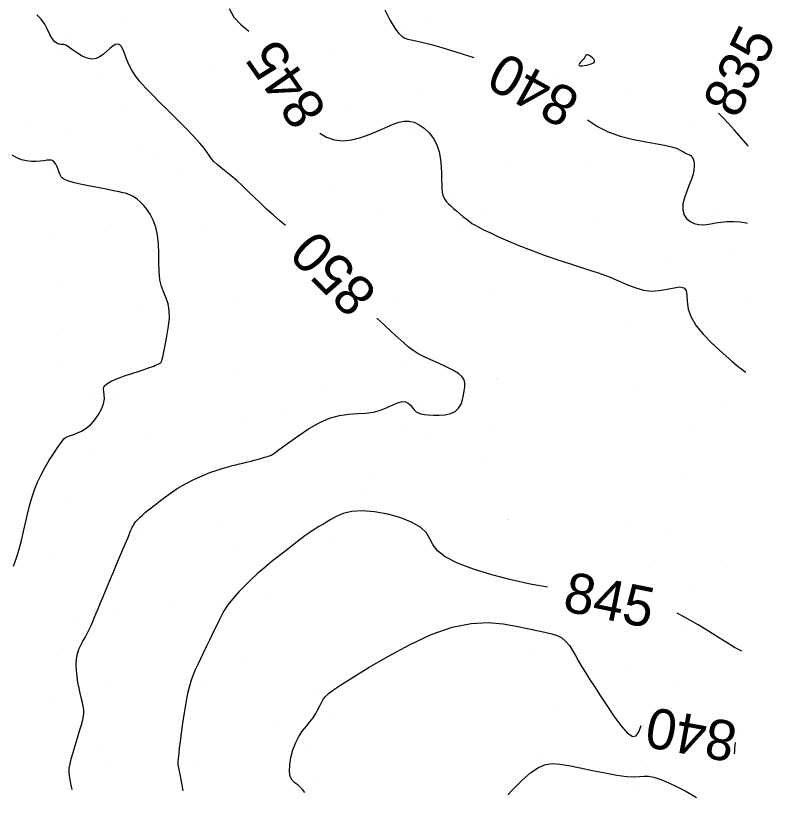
# Model space of a CAD drawing. Extents: x 400243 to 403697, y 4403637 to 4408083.
# Drawn here: x 402954.4 to 403095.7, y 4405853 to 4405998.7 of the extents above; entities that cross this region are included whole.
import ezdxf

# ---------------------------------------------------------------- set-up
doc = ezdxf.new("R2010")
doc.units = 0
doc.layers.add('HH_DiS', color=7, linetype='Continuous')
doc.layers.add('HH_IC', color=7, linetype='Continuous')

msp = doc.modelspace()

# ---------------------------------------------------------------- linework, layer by layer
at = {"layer": 'HH_DiS'}
msp.add_line((403004.38, 4405924.73), (403004.38, 4405924.73), dxfattribs=at)
at = {"layer": 'HH_IC'}
for p, q in [((402974.1, 4405998.57), (402974.1, 4405998.57)), ((403031.74, 4405998.14), (403031.74, 4405998.14)), ((403027, 4405995.77), (403027, 4405995.77)), ((402963.64, 4405994.12), (402963.64, 4405994.12)), ((402963.91, 4405994.25), (402963.91, 4405994.25)), ((403013.43, 4405992.67), (403013.43, 4405992.67)), ((402963.29, 4405991.89), (402963.29, 4405991.89)), ((403086.84, 4405991.77), (403086.84, 4405991.77)), ((403061.02, 4405990.08), (403061.02, 4405990.08)), ((403085.9, 4405990.13), (403085.9, 4405990.13)), ((402970.34, 4405987.96), (402970.34, 4405987.96)), ((402991.13, 4405989.31), (402991.13, 4405989.31)), ((403054.48, 4405987.14), (403054.48, 4405987.14)), ((403029.23, 4405985.05), (403029.23, 4405985.05)), ((403068.85, 4405984.25), (403068.85, 4405984.25)), ((402974.71, 4405981.67), (402974.71, 4405981.67)), ((403016.53, 4405981.52), (403016.53, 4405981.52)), ((403085.02, 4405981.59), (403085.02, 4405981.59)), ((402956.59, 4405978.42), (402956.59, 4405978.42)), ((403080.48, 4405978.69), (403080.48, 4405978.69)), ((402963.85, 4405977.37), (402963.85, 4405977.37)), ((403028.05, 4405977.16), (403028.05, 4405977.16)), ((402978.31, 4405974.53), (402978.31, 4405974.53)), ((402980.08, 4405972.86), (402980.08, 4405972.86)), ((403079.57, 4405971.96), (403079.57, 4405971.96)), ((403046.52, 4405970.77), (403046.52, 4405970.77)), ((403061.14, 4405970.51), (403061.14, 4405970.51)), ((402961.03, 4405970.24), (402961.03, 4405970.24)), ((402985.24, 4405969.68), (402985.24, 4405969.68)), ((402962.63, 4405967.53), (402962.63, 4405967.53)), ((403013.25, 4405966.29), (403013.25, 4405966.29)), ((403035.13, 4405964.99), (403035.13, 4405964.99)), ((403084.27, 4405962.3), (403084.27, 4405962.3)), ((403022.5, 4405961.45), (403022.5, 4405961.45)), ((403041, 4405961.61), (403041, 4405961.61)), ((403062.6, 4405960.83), (403062.6, 4405960.83)), ((402961.38, 4405957.97), (402961.38, 4405957.97)), ((402970.96, 4405958.57), (402970.96, 4405958.57)), ((402988.94, 4405958.63), (402988.94, 4405958.63)), ((403037.24, 4405958.48), (403037.24, 4405958.48)), ((403013.31, 4405957.18), (403013.31, 4405957.18)), ((403088.07, 4405955.16), (403088.07, 4405955.16)), ((403076.03, 4405952.46), (403076.03, 4405952.46)), ((402961.92, 4405949.02), (402961.92, 4405949.02)), ((403018.52, 4405949.85), (403018.52, 4405949.85)), ((403025.07, 4405945.86), (403025.07, 4405945.86)), ((403042.5, 4405946.79), (403042.5, 4405946.79)), ((402977.32, 4405944.53), (402977.32, 4405944.53)), ((402995.62, 4405945.07), (402995.62, 4405945.07)), ((403013.71, 4405945.64), (403013.71, 4405945.64)), ((403090.67, 4405945.08), (403090.67, 4405945.08)), ((402963.38, 4405940.47), (402963.38, 4405940.47)), ((403069.11, 4405941.1), (403069.11, 4405941.1)), ((402963.26, 4405934), (402963.26, 4405934)), ((402980.17, 4405934.22), (402980.17, 4405934.22)), ((403027.5, 4405933.5), (403027.5, 4405933.5)), ((402994.79, 4405932.51), (402994.79, 4405932.51)), ((403044.17, 4405931.04), (403044.17, 4405931.04)), ((403044.19, 4405931.01), (403044.19, 4405931.01)), ((402968.13, 4405928.35), (402968.13, 4405928.35)), ((403011.24, 4405928.82), (403011.24, 4405928.82)), ((403070.31, 4405929.58), (403070.31, 4405929.58)), ((402972.65, 4405927.9), (402972.65, 4405927.9)), ((403086.67, 4405927.06), (403086.67, 4405927.06)), ((403029.73, 4405926.68), (403029.73, 4405926.68)), ((402996.29, 4405923.79), (402996.29, 4405923.79)), ((403026.75, 4405921.4), (403026.75, 4405921.4)), ((403043.19, 4405922.04), (403043.19, 4405922.04)), ((403079.98, 4405921.35), (403079.98, 4405921.35)), ((402979.51, 4405920.8), (402979.51, 4405920.8)), ((403031.95, 4405920.16), (403031.95, 4405920.16)), ((402969.1, 4405917.84), (402969.1, 4405917.84)), ((403001.9, 4405917.02), (403001.9, 4405917.02)), ((403042.41, 4405916.17), (403042.41, 4405916.17)), ((402996.45, 4405913.7), (402996.45, 4405913.7)), ((403020.92, 4405913.16), (403020.92, 4405913.16)), ((403078.99, 4405912.58), (403078.99, 4405912.58)), ((403018.8, 4405909.87), (403018.8, 4405909.87)), ((402964.19, 4405908.04), (402964.19, 4405908.04)), ((403046.07, 4405904.85), (403046.07, 4405904.85)), ((403046.11, 4405904.85), (403046.11, 4405904.85)), ((403068.63, 4405904.3), (403068.63, 4405904.3)), ((402978.14, 4405902.59), (402978.14, 4405902.59)), ((402992.43, 4405903.24), (402992.43, 4405903.24)), ((403076.35, 4405903.07), (403076.35, 4405903.07)), ((403013.18, 4405901.45), (403013.18, 4405901.45)), ((402995.71, 4405899.82), (402995.71, 4405899.82)), ((402961.41, 4405897.89), (402961.41, 4405897.89)), ((403073.66, 4405897.04), (403073.66, 4405897.04)), ((403085.87, 4405897.21), (403085.87, 4405897.21)), ((403051.71, 4405893.53), (403051.71, 4405893.53)), ((403081.19, 4405892.55), (403081.19, 4405892.55)), ((403068.76, 4405890.26), (403068.76, 4405890.26)), ((402983.17, 4405889.37), (402983.17, 4405889.37)), ((403001.71, 4405889.91), (403001.71, 4405889.91)), ((402973.67, 4405887.81), (402973.67, 4405887.81)), ((402992.21, 4405888.7), (402992.21, 4405888.7)), ((402966.01, 4405885.65), (402966.01, 4405885.65)), ((403078.8, 4405884.24), (403078.8, 4405884.24)), ((402963.33, 4405880.79), (402963.33, 4405880.79)), ((403050.97, 4405880.12), (403050.97, 4405880.12)), ((402996.64, 4405878.4), (402996.64, 4405878.4)), ((403068.31, 4405876.46), (403068.31, 4405876.46)), ((402971.71, 4405874.06), (402971.71, 4405874.06)), ((402989.45, 4405873.69), (402989.45, 4405873.69)), ((403077.71, 4405873.62), (403077.71, 4405873.62)), ((402961.34, 4405871.63), (402961.34, 4405871.63)), ((403010.94, 4405872.73), (403010.94, 4405872.73)), ((402966.44, 4405868.65), (402966.44, 4405868.65)), ((403013.43, 4405868.54), (403013.43, 4405868.54)), ((403055.42, 4405869.13), (403055.42, 4405869.13)), ((403003.19, 4405866.18), (403003.19, 4405866.18)), ((403089.02, 4405865.66), (403089.02, 4405865.66)), ((403074.34, 4405862.88), (403074.34, 4405862.88)), ((402970.61, 4405862.02), (402970.61, 4405862.02)), ((403009.2, 4405861.7), (403009.2, 4405861.7)), ((403051.58, 4405860.63), (403051.58, 4405860.63)), ((403070.85, 4405859.86), (403070.85, 4405859.86)), ((402972.23, 4405859.08), (402972.23, 4405859.08)), ((402987.36, 4405859.23), (402987.36, 4405859.23)), ((403010.01, 4405856.69), (403010.01, 4405856.69)), ((403070.61, 4405855.18), (403070.61, 4405855.18))]:
    msp.add_line(p, q, dxfattribs=at)
for points in [[(402994.21, 4406000.04), (402995.1, 4405998.47), (402996.4, 4405997.09), (402997.85, 4405995.83)], [(403023.24, 4405999.81), (403024.26, 4405997.82), (403025.11, 4405996.39), (403025.81, 4405995.45), (403026.42, 4405994.88), (403026.98, 4405994.56), (403027.54, 4405994.38), (403028.18, 4405994.23), (403029, 4405994.06), (403030.13, 4405993.8), (403031.71, 4405993.39), (403033.86, 4405992.78), (403036.65, 4405991.93), (403039.84, 4405990.92)], [(403004.72, 4405959.59), (403003.58, 4405960.55), (403002.4, 4405961.57), (403001.2, 4405962.63), (403000.03, 4405963.74), (402998.88, 4405964.86), (402997.76, 4405965.96), (402996.68, 4405967.02), (402995.61, 4405967.99), (402994.59, 4405968.87), (402993.62, 4405969.64), (402992.74, 4405970.34), (402991.98, 4405970.96), (402991.37, 4405971.52), (402990.92, 4405972.04), (402990.54, 4405972.58), (402990.12, 4405973.21), (402989.54, 4405974.01), (402988.69, 4405975.03), (402987.5, 4405976.32), (402986.05, 4405977.81), (402984.44, 4405979.42), (402982.8, 4405981.05), (402981.23, 4405982.61), (402979.82, 4405984.02), (402978.6, 4405985.3), (402977.56, 4405986.48), (402976.68, 4405987.6), (402975.98, 4405988.68), (402975.44, 4405989.76), (402975.02, 4405990.79), (402974.68, 4405991.72), (402974.38, 4405992.49), (402974.08, 4405993.05), (402973.75, 4405993.36), (402973.37, 4405993.44), (402972.94, 4405993.33), (402972.48, 4405993.04), (402971.96, 4405992.63), (402971.4, 4405992.11), (402970.79, 4405991.57), (402970.12, 4405991.09), (402969.38, 4405990.76), (402968.57, 4405990.65), (402967.7, 4405990.82), (402966.8, 4405991.21), (402965.93, 4405991.72), (402965.15, 4405992.24), (402964.52, 4405992.7), (402964.08, 4405993.02), (402963.77, 4405993.21), (402963.55, 4405993.3), (402963.36, 4405993.33), (402963.14, 4405993.33), (402962.83, 4405993.34), (402962.46, 4405993.41), (402962.05, 4405993.59), (402961.62, 4405993.92), (402961.19, 4405994.47), (402960.78, 4405995.24), (402960.34, 4405996.17), (402959.82, 4405997.16), (402959.16, 4405998.1), (402958.32, 4405998.9)], [(403059.48, 4405989.43), (403059.69, 4405989.35), (403060.03, 4405989.36), (403060.45, 4405989.41), (403060.91, 4405989.51), (403061.36, 4405989.62), (403061.74, 4405989.74), (403062.05, 4405989.87), (403062.26, 4405990.01), (403062.36, 4405990.18), (403062.34, 4405990.39), (403062.2, 4405990.63), (403061.96, 4405990.88), (403061.68, 4405991.12), (403061.38, 4405991.31), (403061.11, 4405991.41), (403060.9, 4405991.42), (403060.75, 4405991.35), (403060.65, 4405991.23), (403060.58, 4405991.09), (403060.54, 4405990.96), (403060.51, 4405990.87), (403060.48, 4405990.8), (403060.42, 4405990.73), (403060.33, 4405990.63), (403060.19, 4405990.49), (403059.98, 4405990.29), (403059.75, 4405990.05), (403059.56, 4405989.8), (403059.45, 4405989.58), (403059.48, 4405989.43)], [(403061.04, 4405979.28), (403062.88, 4405978.08), (403064.92, 4405977.04), (403067.13, 4405976.25), (403069.4, 4405975.67), (403071.62, 4405975.25), (403073.66, 4405974.91), (403075.4, 4405974.6), (403076.75, 4405974.27), (403077.75, 4405973.93), (403078.47, 4405973.6), (403078.97, 4405973.32), (403079.32, 4405973.09), (403079.58, 4405972.95), (403079.78, 4405972.88), (403079.93, 4405972.83), (403080.06, 4405972.8), (403080.19, 4405972.74), (403080.33, 4405972.64), (403080.47, 4405972.48), (403080.61, 4405972.27), (403080.74, 4405971.98), (403080.85, 4405971.62), (403080.92, 4405971.17), (403080.94, 4405970.63), (403080.88, 4405969.97), (403080.72, 4405969.18), (403080.44, 4405968.25), (403080.03, 4405967.17), (403079.56, 4405965.99), (403079.14, 4405964.78), (403078.85, 4405963.62), (403078.8, 4405962.56), (403079.04, 4405961.66), (403079.53, 4405960.93), (403080.19, 4405960.37), (403080.95, 4405959.98), (403081.74, 4405959.77), (403082.5, 4405959.71), (403083.25, 4405959.78), (403084.04, 4405959.93), (403084.91, 4405960.1), (403085.91, 4405960.24), (403087.05, 4405960.33), (403088.27, 4405960.33), (403089.5, 4405960.26), (403090.65, 4405960.09), (403090.85, 4405960.04)], [(403091.03, 4405974.34), (403090.92, 4405974.49), (403089.73, 4405975.92), (403088.46, 4405977.37), (403087.25, 4405978.71), (403086.22, 4405979.8), (403085.46, 4405980.54)], [(403011.1, 4405976.84), (403012.38, 4405976.06), (403013.81, 4405975.57), (403015.38, 4405975.41), (403017.06, 4405975.59), (403018.78, 4405976.03), (403020.49, 4405976.64), (403022.11, 4405977.31), (403023.57, 4405977.95), (403024.82, 4405978.48), (403025.9, 4405978.86), (403026.87, 4405979.06), (403027.78, 4405979.06), (403028.69, 4405978.85), (403029.65, 4405978.4), (403030.6, 4405977.73), (403031.5, 4405976.86), (403032.3, 4405975.82), (403032.93, 4405974.62), (403033.37, 4405973.31), (403033.63, 4405971.94), (403033.77, 4405970.57), (403033.82, 4405969.29), (403033.84, 4405968.14), (403033.86, 4405967.19), (403033.9, 4405966.42), (403033.96, 4405965.79), (403034.08, 4405965.27), (403034.24, 4405964.82), (403034.47, 4405964.41), (403034.76, 4405964.02), (403035.12, 4405963.64), (403035.55, 4405963.24), (403036.04, 4405962.8), (403036.58, 4405962.32), (403037.17, 4405961.82), (403037.78, 4405961.31), (403038.38, 4405960.82), (403038.96, 4405960.38), (403039.49, 4405960), (403040.06, 4405959.64), (403040.75, 4405959.26), (403041.64, 4405958.82), (403042.81, 4405958.27), (403044.33, 4405957.57), (403046.17, 4405956.77), (403048.26, 4405955.89), (403050.55, 4405954.98), (403052.98, 4405954.08), (403055.5, 4405953.22), (403058.03, 4405952.4), (403060.5, 4405951.61), (403062.84, 4405950.83), (403064.98, 4405950.06), (403066.85, 4405949.29), (403068.52, 4405948.56), (403070.04, 4405947.96), (403071.49, 4405947.54), (403072.94, 4405947.36), (403074.42, 4405947.46), (403075.87, 4405947.72), (403077.19, 4405947.99), (403078.28, 4405948.14), (403079.04, 4405948), (403079.42, 4405947.47), (403079.55, 4405946.58), (403079.63, 4405945.41), (403079.84, 4405944.03), (403080.37, 4405942.5), (403081.33, 4405940.91), (403082.63, 4405939.31), (403084.1, 4405937.79), (403085.59, 4405936.4), (403086.92, 4405935.23), (403087.98, 4405934.32), (403088.78, 4405933.64), (403089.38, 4405933.15), (403089.85, 4405932.79), (403090.23, 4405932.52), (403090.5, 4405932.34), (403090.58, 4405932.29)], [(402953.99, 4405896.07), (402954.55, 4405897.63), (402955.03, 4405899.25), (402955.45, 4405900.89), (402955.84, 4405902.54), (402956.21, 4405904.18), (402956.58, 4405905.78), (402956.98, 4405907.33), (402957.42, 4405908.83), (402957.91, 4405910.29), (402958.48, 4405911.72), (402959.13, 4405913.13), (402959.87, 4405914.51), (402960.66, 4405915.82), (402961.43, 4405917.02), (402962.12, 4405918.05), (402962.69, 4405918.87), (402963.1, 4405919.44), (402963.39, 4405919.8), (402963.66, 4405920.04), (402963.97, 4405920.2), (402964.41, 4405920.35), (402965.02, 4405920.56), (402965.79, 4405920.86), (402966.64, 4405921.26), (402967.53, 4405921.8), (402968.39, 4405922.5), (402969.18, 4405923.37), (402969.85, 4405924.35), (402970.38, 4405925.37), (402970.75, 4405926.37), (402970.93, 4405927.27), (402970.92, 4405928.01), (402970.82, 4405928.63), (402970.77, 4405929.15), (402970.91, 4405929.63), (402971.36, 4405930.1), (402972.22, 4405930.58), (402973.38, 4405931.08), (402974.7, 4405931.56), (402976.03, 4405932.01), (402977.21, 4405932.39), (402978.15, 4405932.7), (402978.84, 4405932.93), (402979.37, 4405933.12), (402979.78, 4405933.27), (402980.13, 4405933.4), (402980.46, 4405933.53), (402980.78, 4405933.66), (402981.07, 4405933.8), (402981.32, 4405933.96), (402981.51, 4405934.14), (402981.64, 4405934.35), (402981.73, 4405934.65), (402981.82, 4405935.1), (402981.94, 4405935.75), (402982.12, 4405936.66), (402982.37, 4405937.88), (402982.66, 4405939.31), (402982.91, 4405940.84), (402983.06, 4405942.37), (402983.04, 4405943.77), (402982.82, 4405944.99), (402982.46, 4405946.07), (402982.02, 4405947.12), (402981.61, 4405948.23), (402981.29, 4405949.5), (402981.13, 4405951.01), (402981.08, 4405952.68), (402981.07, 4405954.43), (402981.02, 4405956.18), (402980.85, 4405957.82), (402980.52, 4405959.3), (402980.05, 4405960.59), (402979.47, 4405961.7), (402978.85, 4405962.65), (402978.21, 4405963.42), (402977.61, 4405964.03), (402977.04, 4405964.5), (402976.53, 4405964.86), (402976.06, 4405965.12), (402975.65, 4405965.32), (402975.29, 4405965.47), (402974.9, 4405965.6), (402974.39, 4405965.72), (402973.67, 4405965.88), (402972.65, 4405966.08), (402971.28, 4405966.35), (402969.67, 4405966.67), (402968, 4405967), (402966.42, 4405967.34), (402965.09, 4405967.64), (402964.13, 4405967.91), (402963.49, 4405968.15), (402963.1, 4405968.4), (402962.86, 4405968.69), (402962.69, 4405969.06), (402962.52, 4405969.51), (402962.33, 4405970.02), (402962.12, 4405970.54), (402961.89, 4405971.01), (402961.64, 4405971.38), (402961.38, 4405971.63), (402961.07, 4405971.76), (402960.69, 4405971.79), (402960.23, 4405971.76), (402959.66, 4405971.69), (402958.97, 4405971.61), (402958.17, 4405971.55), (402957.31, 4405971.55), (402956.4, 4405971.63), (402955.49, 4405971.84), (402954.59, 4405972.19), (402953.71, 4405972.69)], [(402964.94, 4405854.44), (402964.75, 4405855.26), (402964.54, 4405856.22), (402964.41, 4405857.02), (402964.35, 4405857.73), (402964.39, 4405858.43), (402964.52, 4405859.21), (402964.75, 4405860.16), (402965.08, 4405861.33), (402965.48, 4405862.66), (402965.91, 4405864.03), (402966.31, 4405865.34), (402966.65, 4405866.5), (402966.89, 4405867.41), (402967.04, 4405868.12), (402967.1, 4405868.7), (402967.1, 4405869.2), (402967.04, 4405869.7), (402966.93, 4405870.25), (402966.79, 4405870.87), (402966.61, 4405871.58), (402966.42, 4405872.39), (402966.22, 4405873.31), (402966.01, 4405874.35), (402965.83, 4405875.47), (402965.71, 4405876.62), (402965.66, 4405877.75), (402965.72, 4405878.8), (402965.9, 4405879.74), (402966.18, 4405880.58), (402966.54, 4405881.35), (402966.94, 4405882.08), (402967.35, 4405882.8), (402967.74, 4405883.53), (402968.11, 4405884.27), (402968.46, 4405885.02), (402968.79, 4405885.78), (402969.11, 4405886.54), (402969.43, 4405887.31), (402969.76, 4405888.14), (402970.15, 4405889.09), (402970.62, 4405890.24), (402971.19, 4405891.62), (402971.89, 4405893.29), (402972.67, 4405895.12), (402973.46, 4405896.98), (402974.2, 4405898.72), (402974.82, 4405900.2), (402975.29, 4405901.32), (402975.61, 4405902.12), (402975.83, 4405902.67), (402975.99, 4405903.05), (402976.13, 4405903.34), (402976.27, 4405903.61), (402976.43, 4405903.87), (402976.61, 4405904.13), (402976.81, 4405904.38), (402977.04, 4405904.64), (402977.29, 4405904.91), (402977.61, 4405905.22), (402978.04, 4405905.61), (402978.63, 4405906.12), (402979.42, 4405906.77), (402980.44, 4405907.59), (402981.66, 4405908.53), (402983.03, 4405909.53), (402984.52, 4405910.53), (402986.06, 4405911.45), (402987.63, 4405912.26), (402989.16, 4405912.94), (402990.62, 4405913.51), (402991.94, 4405913.97), (402993.09, 4405914.34), (402994.03, 4405914.61), (402994.81, 4405914.82), (402995.48, 4405914.98), (402996.11, 4405915.13), (402996.76, 4405915.28), (402997.47, 4405915.45), (402998.22, 4405915.65), (402998.96, 4405915.85), (402999.67, 4405916.05), (403000.29, 4405916.22), (403000.79, 4405916.37), (403001.19, 4405916.49), (403001.5, 4405916.58), (403001.72, 4405916.66), (403001.89, 4405916.72), (403002.01, 4405916.77), (403002.1, 4405916.8), (403002.16, 4405916.83), (403002.2, 4405916.85), (403002.23, 4405916.87), (403002.28, 4405916.89), (403002.42, 4405916.98), (403002.73, 4405917.2), (403003.3, 4405917.62), (403004.21, 4405918.31), (403005.53, 4405919.29), (403007.17, 4405920.47), (403009.03, 4405921.68), (403010.99, 4405922.8), (403012.94, 4405923.67), (403014.8, 4405924.19), (403016.54, 4405924.44), (403018.17, 4405924.55), (403019.7, 4405924.63), (403021.13, 4405924.81), (403022.45, 4405925.18), (403023.66, 4405925.66), (403024.74, 4405926.15), (403025.68, 4405926.56), (403026.47, 4405926.78), (403027.1, 4405926.73), (403027.6, 4405926.46), (403028.01, 4405926.07), (403028.37, 4405925.62), (403028.71, 4405925.2), (403029.06, 4405924.88), (403029.47, 4405924.65), (403029.97, 4405924.48), (403030.59, 4405924.37), (403031.37, 4405924.3), (403032.33, 4405924.24), (403033.4, 4405924.23), (403034.49, 4405924.32), (403035.51, 4405924.54), (403036.37, 4405924.94), (403037.01, 4405925.53), (403037.45, 4405926.27), (403037.74, 4405927.11), (403037.93, 4405927.97), (403038.05, 4405928.79), (403038.15, 4405929.53), (403038.17, 4405930.19), (403038.02, 4405930.8), (403037.65, 4405931.4), (403036.97, 4405932), (403035.94, 4405932.62), (403034.66, 4405933.26), (403033.26, 4405933.9), (403031.84, 4405934.53), (403030.55, 4405935.13), (403029.47, 4405935.7), (403028.55, 4405936.29), (403027.67, 4405936.94), (403026.77, 4405937.7), (403025.72, 4405938.64), (403024.49, 4405939.78), (403023.12, 4405941.05), (403021.72, 4405942.35)], [(403053.58, 4405892.15), (403050.32, 4405892.73), (403046.78, 4405893.52), (403043.18, 4405894.46), (403039.77, 4405895.52), (403036.79, 4405896.65), (403034.5, 4405897.81), (403033.05, 4405898.96), (403032.2, 4405900.09), (403031.63, 4405901.19), (403031, 4405902.26), (403029.98, 4405903.27), (403028.34, 4405904.23), (403026.2, 4405905.07), (403023.79, 4405905.75), (403021.32, 4405906.2), (403019.02, 4405906.38), (403017.07, 4405906.24), (403015.47, 4405905.87), (403014.18, 4405905.36), (403013.16, 4405904.8), (403012.38, 4405904.3), (403011.78, 4405903.93), (403011.32, 4405903.66), (403010.94, 4405903.44), (403010.58, 4405903.24), (403010.18, 4405902.99), (403009.7, 4405902.67), (403009.09, 4405902.25), (403008.35, 4405901.71), (403007.45, 4405901.04), (403006.38, 4405900.23), (403005.13, 4405899.27), (403003.75, 4405898.2), (403002.3, 4405897.04), (403000.85, 4405895.83), (402999.45, 4405894.63), (402998.18, 4405893.45), (402997.04, 4405892.33), (402996.04, 4405891.28), (402995.19, 4405890.35), (402994.51, 4405889.54), (402993.98, 4405888.87), (402993.59, 4405888.31), (402993.28, 4405887.82), (402993.03, 4405887.36), (402992.78, 4405886.88), (402992.52, 4405886.35), (402992.23, 4405885.75), (402991.89, 4405885.05), (402991.5, 4405884.25), (402991.05, 4405883.33), (402990.53, 4405882.27), (402989.98, 4405881.13), (402989.41, 4405879.95), (402988.85, 4405878.8), (402988.34, 4405877.73), (402987.88, 4405876.76), (402987.48, 4405875.83), (402987.12, 4405874.84), (402986.78, 4405873.7), (402986.45, 4405872.31), (402986.12, 4405870.61), (402985.81, 4405868.72), (402985.51, 4405866.78), (402985.25, 4405864.94), (402985.04, 4405863.36), (402984.9, 4405862.14), (402984.8, 4405861.26), (402984.74, 4405860.64), (402984.7, 4405860.22), (402984.68, 4405859.93), (402984.66, 4405859.71), (402984.64, 4405859.53), (402984.62, 4405859.38), (402984.62, 4405859.22), (402984.64, 4405859.04), (402984.68, 4405858.82), (402984.75, 4405858.46), (402984.87, 4405857.86), (402985.05, 4405856.95), (402985.3, 4405855.61), (402985.56, 4405854.18)], [(403089.84, 4405880.23), (403089.44, 4405880.38), (403088.43, 4405880.93), (403087.08, 4405881.75), (403085.46, 4405882.78), (403083.64, 4405883.93), (403081.7, 4405885.12), (403079.71, 4405886.26), (403077.77, 4405887.28)], [(403008.31, 4405853.89), (403007.91, 4405854.44), (403007.14, 4405855.17), (403006.48, 4405855.68), (403005.95, 4405856.16), (403005.59, 4405856.82), (403005.45, 4405857.79), (403005.5, 4405859.03), (403005.73, 4405860.41), (403006.11, 4405861.82), (403006.62, 4405863.16), (403007.23, 4405864.32), (403007.91, 4405865.34), (403008.6, 4405866.23), (403009.27, 4405867.05), (403009.86, 4405867.82), (403010.35, 4405868.58), (403010.76, 4405869.32), (403011.11, 4405870.02), (403011.43, 4405870.67), (403011.76, 4405871.26), (403012.15, 4405871.77), (403012.74, 4405872.33), (403013.69, 4405873.04), (403015.18, 4405874.02), (403017.36, 4405875.4), (403020.34, 4405877.23), (403023.92, 4405879.32), (403027.86, 4405881.43), (403031.9, 4405883.3), (403035.8, 4405884.68), (403039.34, 4405885.4), (403042.5, 4405885.56), (403045.29, 4405885.33), (403047.73, 4405884.9), (403049.83, 4405884.43), (403051.61, 4405884.06), (403053.11, 4405883.77), (403054.37, 4405883.48), (403055.41, 4405883.14), (403056.28, 4405882.68), (403057.02, 4405882.05), (403057.67, 4405881.26), (403058.25, 4405880.36), (403058.8, 4405879.39), (403059.36, 4405878.37), (403059.97, 4405877.33), (403060.64, 4405876.23), (403061.42, 4405875.01), (403062.33, 4405873.61), (403063.39, 4405871.97), (403064.63, 4405870.08), (403065.95, 4405868.13), (403067.26, 4405866.36), (403068.45, 4405865), (403069.43, 4405864.3), (403070.14, 4405864.42), (403070.64, 4405865.19), (403071.04, 4405866.36)], [(403088.59, 4405863.16), (403088.54, 4405862.62), (403088.49, 4405862.12), (403088.46, 4405861.7), (403088.43, 4405861.41), (403088.42, 4405861.23), (403088.41, 4405861.14), (403088.4, 4405861.11), (403088.4, 4405861.1)], [(403046.18, 4405853.41), (403047.03, 4405854.37), (403048.83, 4405856.15), (403050.5, 4405857.57), (403051.92, 4405858.54), (403053.2, 4405859.08), (403054.47, 4405859.27), (403055.88, 4405859.18), (403057.57, 4405858.89), (403059.65, 4405858.47), (403061.96, 4405857.99), (403064.32, 4405857.52), (403066.53, 4405857.13), (403068.38, 4405856.88), (403069.75, 4405856.81), (403070.76, 4405856.86), (403071.59, 4405856.93), (403072.4, 4405856.92), (403073.4, 4405856.74), (403074.69, 4405856.3), (403076.19, 4405855.68), (403077.75, 4405854.95), (403079.23, 4405854.2), (403080.47, 4405853.52), (403081.35, 4405852.96), (403081.36, 4405852.96)]]:
    msp.add_lwpolyline(points, dxfattribs=at)

# ---------------------------------------------------------------- texts
for s, rotation, p in [('835', 63.8959, (403089.01, 4405979.26)), ('845', 124.9139, (403012.65, 4405981.18)), ('840', 151.2275, (403060.05, 4405984.1)), ('850', 134.5875, (403022.14, 4405947.26)), ('845', 348.6217, (403056.2, 4405887.79)), ('840', 169.6845, (403089.25, 4405866.85))]:
    msp.add_text(s, height=7.5, rotation=rotation, dxfattribs=at).set_placement(p)

doc.saveas('drawing.dxf')
